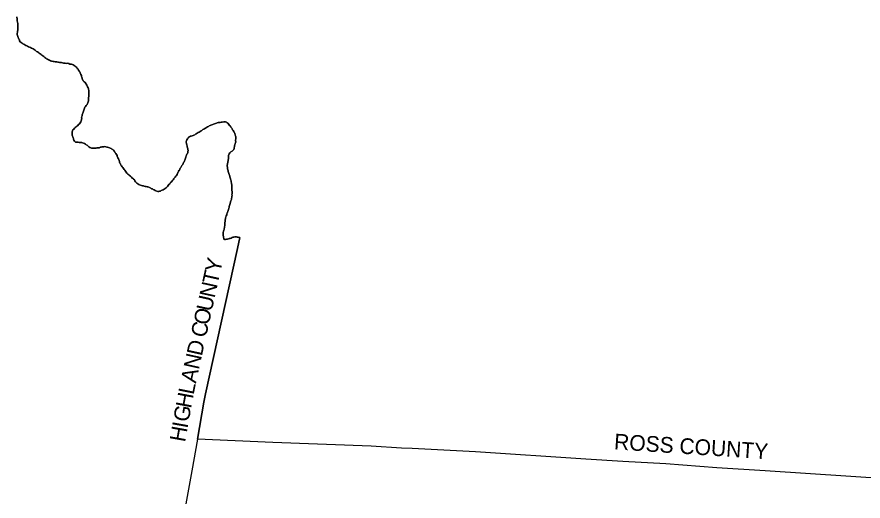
# Model space of a CAD drawing. Extents: x -51392 to 1635000, y 156707 to 696232.
# Drawn here: x 151547 to 205342, y 359420 to 390170 of the extents above; entities that cross this region are included whole.
import ezdxf

# ---------------------------------------------------------------- set-up
doc = ezdxf.new("R2010")
doc.units = 0
doc.layers.add('GM_X_Adjacent_County', color=7, linetype='Continuous')
doc.layers.add('GM_X_Adjacent_County_Text', color=7, linetype='Continuous')

msp = doc.modelspace()

# ---------------------------------------------------------------- linework, layer by layer
at = {"layer": 'GM_X_Adjacent_County'}
for points in [[(209682, 360646), (199125, 361332), (196035, 361533), (192807, 361777), (190062, 361926), (187719, 362082), (180708, 362551), (176670, 362753), (175993, 362777), (174068, 362897), (167808, 363138), (163023, 363354), (163438, 365695), (163533, 366233), (165575, 375472), (165728, 376165), (165686, 376168), (165620, 376175), (165557, 376187), (165501, 376193), (165447, 376198), (165393, 376206), (165333, 376188), (165279, 376188), (165221, 376151), (165158, 376119), (165104, 376097), (165050, 376093), (164996, 376074), (164934, 376060), (164880, 376050), (164806, 376038), (164752, 376033), (164698, 376057), (164691, 376109), (164685, 376167), (164671, 376220), (164662, 376280), (164662, 376336), (164654, 376390), (164665, 376480), (164687, 376558), (164708, 376616), (164720, 376672), (164732, 376731), (164741, 376785), (164745, 376843), (164757, 376913), (164768, 376979), (164770, 377043), (164771, 377109), (164777, 377167), (164777, 377217), (164781, 377272), (164798, 377340), (164816, 377400), (164837, 377462), (164857, 377534), (164883, 377590), (164900, 377654), (164920, 377712), (164932, 377768), (164957, 377820), (164971, 377872), (164993, 377948), (165020, 378014), (165032, 378074), (165043, 378136), (165055, 378194), (165073, 378252), (165094, 378310), (165118, 378427), (165147, 378489), (165185, 378579), (165196, 378643), (165200, 378713), (165206, 378763), (165229, 378823), (165217, 378877), (165229, 378959), (165228, 379011), (165226, 379078), (165217, 379148), (165215, 379198), (165213, 379272), (165218, 379334), (165212, 379396), (165208, 379447), (165203, 379505), (165197, 379565), (165198, 379633), (165170, 379685), (165158, 379754), (165147, 379806), (165129, 379896), (165104, 379958), (165090, 380011), (165074, 380061), (165056, 380113), (165037, 380163), (165017, 380217), (164996, 380282), (164978, 380342), (164970, 380396), (164951, 380460), (164943, 380513), (164924, 380625), (164918, 380685), (164918, 380761), (164931, 380813), (164939, 380869), (164949, 380921), (164962, 380974), (164976, 381036), (164980, 381086), (164999, 381148), (164999, 381198), (164997, 381248), (165004, 381308), (165008, 381362), (165016, 381430), (165047, 381482), (165091, 381548), (165155, 381612), (165222, 381648), (165286, 381698), (165332, 381755), (165351, 381812), (165367, 381866), (165383, 381930), (165388, 381982), (165410, 382056), (165430, 382122), (165443, 382182), (165455, 382236), (165451, 382296), (165446, 382360), (165460, 382412), (165472, 382476), (165457, 382562), (165442, 382612), (165427, 382665), (165391, 382780), (165364, 382836), (165331, 382893), (165289, 382956), (165261, 383007), (165234, 383059), (165201, 383112), (165156, 383173), (165117, 383224), (165068, 383283), (165020, 383340), (164979, 383397), (164916, 383452), (164864, 383495), (164811, 383506), (164759, 383505), (164705, 383506), (164592, 383492), (164528, 383477), (164462, 383458), (164404, 383457), (164340, 383456), (164282, 383445), (164227, 383424), (164169, 383405), (164109, 383386), (164054, 383369), (163994, 383344), (163941, 383319), (163885, 383298), (163831, 383270), (163778, 383245), (163717, 383204), (163661, 383181), (163609, 383148), (163544, 383115), (163483, 383084), (163425, 383049), (163356, 383014), (163303, 382967), (163253, 382938), (163198, 382899), (163132, 382860), (163075, 382827), (163006, 382786), (162950, 382751), (162897, 382720), (162847, 382690), (162794, 382659), (162744, 382632), (162687, 382613), (162627, 382606), (162577, 382597), (162522, 382558), (162460, 382525), (162444, 382474), (162399, 382420), (162359, 382366), (162327, 382310), (162308, 382256), (162308, 382204), (162318, 382152), (162326, 382101), (162349, 382045), (162365, 381965), (162374, 381911), (162396, 381852), (162408, 381800), (162417, 381744), (162427, 381676), (162417, 381622), (162402, 381566), (162382, 381506), (162358, 381454), (162323, 381394), (162309, 381338), (162283, 381262), (162266, 381190), (162238, 381130), (162219, 381078), (162203, 381025), (162173, 380974), (162143, 380918), (162122, 380857), (162088, 380800), (162035, 380738), (162011, 380686), (161975, 380616), (161934, 380560), (161894, 380506), (161884, 380446), (161829, 380392), (161813, 380334), (161781, 380280), (161753, 380228), (161726, 380158), (161686, 380102), (161639, 380046), (161609, 379990), (161551, 379932), (161519, 379878), (161472, 379822), (161418, 379756), (161378, 379704), (161317, 379651), (161259, 379575), (161215, 379521), (161168, 379459), (161126, 379403), (161072, 379367), (161027, 379311), (160973, 379277), (160911, 379226), (160845, 379198), (160789, 379162), (160724, 379140), (160672, 379113), (160610, 379109), (160560, 379075), (160504, 379081), (160440, 379096), (160384, 379114), (160331, 379142), (160271, 379181), (160219, 379209), (160161, 379241), (160107, 379260), (160050, 379288), (159984, 379335), (159926, 379363), (159874, 379369), (159820, 379379), (159760, 379398), (159708, 379408), (159645, 379420), (159591, 379437), (159531, 379451), (159465, 379467), (159413, 379488), (159349, 379512), (159293, 379536), (159234, 379573), (159180, 379609), (159128, 379646), (159082, 379696), (159049, 379750), (159021, 379813), (158959, 379857), (158928, 379909), (158876, 379934), (158822, 379992), (158773, 380046), (158709, 380093), (158661, 380145), (158602, 380187), (158542, 380256), (158494, 380320), (158457, 380375), (158415, 380427), (158363, 380475), (158316, 380544), (158278, 380596), (158230, 380656), (158185, 380713), (158157, 380765), (158122, 380837), (158096, 380890), (158078, 380948), (158059, 380998), (158039, 381056), (158031, 381109), (158002, 381159), (157970, 381211), (157944, 381265), (157929, 381320), (157917, 381372), (157869, 381434), (157838, 381496), (157802, 381547), (157770, 381597), (157735, 381647), (157693, 381698), (157641, 381742), (157587, 381778), (157534, 381811), (157480, 381839), (157426, 381865), (157370, 381884), (157314, 381896), (157262, 381904), (157208, 381917), (157141, 381931), (157077, 381925), (156999, 381926), (156947, 381920), (156897, 381898), (156847, 381890), (156787, 381859), (156737, 381855), (156685, 381857), (156635, 381847), (156583, 381838), (156533, 381830), (156469, 381828), (156415, 381832), (156351, 381837), (156297, 381843), (156238, 381865), (156182, 381884), (156116, 381924), (156060, 381975), (156008, 382019), (155949, 382053), (155897, 382090), (155841, 382126), (155785, 382142), (155717, 382175), (155665, 382185), (155608, 382197), (155556, 382202), (155504, 382204), (155448, 382210), (155390, 382206), (155322, 382211), (155262, 382225), (155204, 382280), (155158, 382336), (155151, 382386), (155145, 382440), (155120, 382498), (155093, 382556), (155087, 382607), (155059, 382657), (155054, 382715), (155049, 382771), (155051, 382825), (155064, 382881), (155080, 382935), (155109, 382991), (155165, 383049), (155206, 383108), (155256, 383144), (155304, 383196), (155359, 383237), (155411, 383283), (155472, 383330), (155522, 383376), (155576, 383440), (155619, 383501), (155636, 383567), (155648, 383629), (155651, 383683), (155665, 383743), (155658, 383808), (155685, 383895), (155697, 383949), (155716, 384009), (155746, 384063), (155757, 384131), (155777, 384195), (155796, 384257), (155819, 384313), (155839, 384375), (155862, 384429), (155912, 384488), (155953, 384546), (156003, 384604), (156040, 384664), (156060, 384717), (156077, 384781), (156095, 384833), (156102, 384893), (156104, 384948), (156105, 385000), (156107, 385052), (156112, 385114), (156119, 385184), (156123, 385284), (156128, 385344), (156125, 385396), (156117, 385460), (156112, 385513), (156104, 385567), (156091, 385617), (156073, 385671), (156044, 385722), (156018, 385780), (155983, 385832), (155951, 385897), (155918, 385947), (155880, 386002), (155815, 386055), (155764, 386113), (155728, 386172), (155697, 386222), (155687, 386282), (155666, 386337), (155650, 386389), (155643, 386447), (155613, 386513), (155594, 386566), (155576, 386616), (155539, 386678), (155505, 386729), (155468, 386789), (155431, 386846), (155387, 386900), (155348, 386951), (155292, 387003), (155241, 387040), (155181, 387081), (155129, 387127), (155076, 387156), (155016, 387172), (154964, 387177), (154908, 387180), (154854, 387206), (154797, 387219), (154739, 387225), (154675, 387216), (154615, 387228), (154553, 387231), (154499, 387242), (154441, 387248), (154375, 387267), (154319, 387273), (154264, 387282), (154198, 387305), (154140, 387305), (154086, 387312), (154028, 387320), (153968, 387317), (153906, 387329), (153846, 387338), (153795, 387355), (153737, 387369), (153679, 387388), (153611, 387420), (153548, 387449), (153486, 387482), (153432, 387514), (153381, 387553), (153327, 387596), (153264, 387650), (153202, 387697), (153135, 387746), (153081, 387788), (153026, 387831), (152962, 387876), (152908, 387916), (152855, 387951), (152801, 387983), (152750, 388024), (152696, 388059), (152638, 388099), (152581, 388142), (152529, 388164), (152467, 388189), (152402, 388226), (152350, 388248), (152288, 388273), (152229, 388307), (152171, 388332), (152109, 388363), (152052, 388401), (151984, 388432), (151924, 388459), (151871, 388495), (151817, 388540), (151750, 388597), (151720, 388651), (151703, 388709), (151675, 388760), (151646, 388816), (151626, 388874), (151599, 388929), (151579, 388989), (151552, 389049), (151563, 389107), (151569, 389147), (151573, 389171), (151584, 389223), (151590, 389276), (151595, 389338), (151601, 389394), (151602, 389494), (151607, 389544), (151609, 389610), (151606, 389678), (151604, 389736), (151590, 389853), (151568, 389903), (151569, 389965), (151563, 390017), (151554, 390079), (151548, 390130), (151547, 390180)], [(151547, 390180), (151548, 390130), (151554, 390079), (151563, 390017), (151569, 389965), (151568, 389903), (151590, 389853), (151604, 389736), (151606, 389678), (151609, 389610), (151607, 389544), (151602, 389494), (151601, 389394), (151595, 389338), (151590, 389276), (151584, 389223), (151573, 389171), (151569, 389147), (151563, 389107), (151552, 389049), (151579, 388989), (151599, 388929), (151626, 388874), (151646, 388816), (151675, 388760), (151703, 388709), (151720, 388651), (151750, 388597), (151817, 388540), (151871, 388495), (151924, 388459), (151984, 388432), (152052, 388401), (152109, 388363), (152171, 388332), (152229, 388307), (152288, 388273), (152350, 388248), (152402, 388226), (152467, 388189), (152529, 388164), (152581, 388142), (152638, 388099), (152696, 388059), (152750, 388024), (152801, 387983), (152855, 387951), (152908, 387916), (152962, 387876), (153026, 387831), (153081, 387788), (153135, 387746), (153202, 387697), (153264, 387650), (153327, 387596), (153381, 387553), (153432, 387514), (153486, 387482), (153548, 387449), (153611, 387420), (153679, 387388), (153737, 387369), (153795, 387355), (153846, 387338), (153906, 387329), (153968, 387317), (154028, 387320), (154086, 387312), (154140, 387305), (154198, 387305), (154264, 387282), (154319, 387273), (154375, 387267), (154441, 387248), (154499, 387242), (154553, 387231), (154615, 387228), (154675, 387216), (154739, 387225), (154797, 387219), (154854, 387206), (154908, 387180), (154964, 387177), (155016, 387172), (155076, 387156), (155129, 387127), (155181, 387081), (155241, 387040), (155292, 387003), (155348, 386951), (155387, 386900), (155431, 386846), (155468, 386789), (155505, 386729), (155539, 386678), (155576, 386616), (155594, 386566), (155613, 386513), (155643, 386447), (155650, 386389), (155666, 386337), (155687, 386282), (155697, 386222), (155728, 386172), (155764, 386113), (155815, 386055), (155880, 386002), (155918, 385947), (155951, 385897), (155983, 385832), (156018, 385780), (156044, 385722), (156073, 385671), (156091, 385617), (156104, 385567), (156112, 385513), (156117, 385460), (156125, 385396), (156128, 385344), (156123, 385284), (156119, 385184), (156112, 385114), (156107, 385052), (156105, 385000), (156104, 384948), (156102, 384893), (156095, 384833), (156077, 384781), (156060, 384717), (156040, 384664), (156003, 384604), (155953, 384546), (155912, 384488), (155862, 384429), (155839, 384375), (155819, 384313), (155796, 384257), (155777, 384195), (155757, 384131), (155746, 384063), (155716, 384009), (155697, 383949), (155685, 383895), (155658, 383808), (155665, 383743), (155651, 383683), (155648, 383629), (155636, 383567), (155619, 383501), (155576, 383440), (155522, 383376), (155472, 383330), (155411, 383283), (155359, 383237), (155304, 383196), (155256, 383144), (155206, 383108), (155165, 383049), (155109, 382991), (155080, 382935), (155064, 382881), (155051, 382825), (155049, 382771), (155054, 382715), (155059, 382657), (155087, 382607), (155093, 382556), (155120, 382498), (155145, 382440), (155151, 382386), (155158, 382336), (155204, 382280), (155262, 382225), (155322, 382211), (155390, 382206), (155448, 382210), (155504, 382204), (155556, 382202), (155608, 382197), (155665, 382185), (155717, 382175), (155785, 382142), (155841, 382126), (155897, 382090), (155949, 382053), (156008, 382019), (156060, 381975), (156116, 381924), (156182, 381884), (156238, 381865), (156297, 381843), (156351, 381837), (156415, 381832), (156469, 381828), (156533, 381830), (156583, 381838), (156635, 381847), (156685, 381857), (156737, 381855), (156787, 381859), (156847, 381890), (156897, 381898), (156947, 381920), (156999, 381926), (157077, 381925), (157141, 381931), (157208, 381917), (157262, 381904), (157314, 381896), (157370, 381884), (157426, 381865), (157480, 381839), (157534, 381811), (157587, 381778), (157641, 381742), (157693, 381698), (157735, 381647), (157770, 381597), (157802, 381547), (157838, 381496), (157869, 381434), (157917, 381372), (157929, 381320), (157944, 381265), (157970, 381211), (158002, 381159), (158031, 381109), (158039, 381056), (158059, 380998), (158078, 380948), (158096, 380890), (158122, 380837), (158157, 380765), (158185, 380713), (158230, 380656), (158278, 380596), (158316, 380544), (158363, 380475), (158415, 380427), (158457, 380375), (158494, 380320), (158542, 380256), (158602, 380187), (158661, 380145), (158709, 380093), (158773, 380046), (158822, 379992), (158876, 379934), (158928, 379909), (158959, 379857), (159021, 379813), (159049, 379750), (159082, 379696), (159128, 379646), (159180, 379609), (159234, 379573), (159293, 379536), (159349, 379512), (159413, 379488), (159465, 379467), (159531, 379451), (159591, 379437), (159645, 379420), (159708, 379408), (159760, 379398), (159820, 379379), (159874, 379369), (159926, 379363), (159984, 379335), (160050, 379288), (160107, 379260), (160161, 379241), (160219, 379209), (160271, 379181), (160331, 379142), (160384, 379114), (160440, 379096), (160504, 379081), (160560, 379075), (160610, 379109), (160672, 379113), (160724, 379140), (160789, 379162), (160845, 379198), (160911, 379226), (160973, 379277), (161027, 379311), (161072, 379367), (161126, 379403), (161168, 379459), (161215, 379521), (161259, 379575), (161317, 379651), (161378, 379704), (161418, 379756), (161472, 379822), (161519, 379878), (161551, 379932), (161609, 379990), (161639, 380046), (161686, 380102), (161726, 380158), (161753, 380228), (161781, 380280), (161813, 380334), (161829, 380392), (161884, 380446), (161894, 380506), (161934, 380560), (161975, 380616), (162011, 380686), (162035, 380738), (162088, 380800), (162122, 380857), (162143, 380918), (162173, 380974), (162203, 381025), (162219, 381078), (162238, 381130), (162266, 381190), (162283, 381262), (162309, 381338), (162323, 381394), (162358, 381454), (162382, 381506), (162402, 381566), (162417, 381622), (162427, 381676), (162417, 381744), (162408, 381800), (162396, 381852), (162374, 381911), (162365, 381965), (162349, 382045), (162326, 382101), (162318, 382152), (162308, 382204), (162308, 382256), (162327, 382310), (162359, 382366), (162399, 382420), (162444, 382474), (162460, 382525), (162522, 382558), (162577, 382597), (162627, 382606), (162687, 382613), (162744, 382632), (162794, 382659), (162847, 382690), (162897, 382720), (162950, 382751), (163006, 382786), (163075, 382827), (163132, 382860), (163198, 382899), (163253, 382938), (163303, 382967), (163356, 383014), (163425, 383049), (163483, 383084), (163544, 383115), (163609, 383148), (163661, 383181), (163717, 383204), (163778, 383245), (163831, 383270), (163885, 383298), (163941, 383319), (163994, 383344), (164054, 383369), (164109, 383386), (164169, 383405), (164227, 383424), (164282, 383445), (164340, 383456), (164404, 383457), (164462, 383458), (164528, 383477), (164592, 383492), (164705, 383506), (164759, 383505), (164811, 383506), (164864, 383495), (164916, 383452), (164979, 383397), (165020, 383340), (165068, 383283), (165117, 383224), (165156, 383173), (165201, 383112), (165234, 383059), (165261, 383007), (165289, 382956), (165331, 382893), (165364, 382836), (165391, 382780), (165427, 382665), (165442, 382612), (165457, 382562), (165472, 382476), (165460, 382412), (165446, 382360), (165451, 382296), (165455, 382236), (165443, 382182), (165430, 382122), (165410, 382056), (165388, 381982), (165383, 381930), (165367, 381866), (165351, 381812), (165332, 381755), (165286, 381698), (165222, 381648), (165155, 381612), (165091, 381548), (165047, 381482), (165016, 381430), (165008, 381362), (165004, 381308), (164997, 381248), (164999, 381198), (164999, 381148), (164980, 381086), (164976, 381036), (164962, 380974), (164949, 380921), (164939, 380869), (164931, 380813), (164918, 380761), (164918, 380685), (164924, 380625), (164943, 380513), (164951, 380460), (164970, 380396), (164978, 380342), (164996, 380282), (165017, 380217), (165037, 380163), (165056, 380113), (165074, 380061), (165090, 380011), (165104, 379958), (165129, 379896), (165147, 379806), (165158, 379754), (165170, 379685), (165198, 379633), (165197, 379565), (165203, 379505), (165208, 379447), (165212, 379396), (165218, 379334), (165213, 379272), (165215, 379198), (165217, 379148), (165226, 379078), (165228, 379011), (165229, 378959), (165217, 378877), (165229, 378823), (165206, 378763), (165200, 378713), (165196, 378643), (165185, 378579), (165147, 378489), (165118, 378427), (165094, 378310), (165073, 378252), (165055, 378194), (165043, 378136), (165032, 378074), (165020, 378014), (164993, 377948), (164971, 377872), (164957, 377820), (164932, 377768), (164920, 377712), (164900, 377654), (164883, 377590), (164857, 377534), (164837, 377462), (164816, 377400), (164798, 377340), (164781, 377272), (164777, 377217), (164777, 377167), (164771, 377109), (164770, 377043), (164768, 376979), (164757, 376913), (164745, 376843), (164741, 376785), (164732, 376731), (164720, 376672), (164708, 376616), (164687, 376558), (164665, 376480), (164654, 376390), (164662, 376336), (164662, 376280), (164671, 376220), (164685, 376167), (164691, 376109), (164698, 376057), (164752, 376033), (164806, 376038), (164880, 376050), (164934, 376060), (164996, 376074), (165050, 376093), (165104, 376097), (165158, 376119), (165221, 376151), (165279, 376188), (165333, 376188), (165393, 376206), (165447, 376198), (165501, 376193), (165557, 376187), (165620, 376175), (165686, 376168), (165728, 376165), (165575, 375472), (163533, 366233), (163438, 365695), (163023, 363354), (162663, 361330), (162292, 359241)]]:
    msp.add_lwpolyline(points, dxfattribs=at)

# ---------------------------------------------------------------- texts
at = {"layer": 'GM_X_Adjacent_County_Text'}
for s, rotation, p in [('Y', 77.5607, (164465, 373868)), ('T', 77.5621, (164303, 373137)), ('N', 77.5607, (164113, 372274)), ('U', 77.5618, (163922, 371410)), ('O', 77.5621, (163732, 370546)), ('C', 77.5608, (163557, 369752)), ('D', 77.5618, (163301, 368591)), ('N', 77.5685, (163110, 367728)), ('A', 77.8506, (162925, 366864)), ('L', 78.6364, (162778, 366135)), ('H', 79.3622, (162615, 365269)), ('G', 79.8562, (162460, 364400)), ('I', 79.8915, (162388, 363998)), ('H', 79.8894, (162233, 363127)), ('ROSS COUNTY', 356.2857, (189488, 362707))]:
    msp.add_text(s, height=1000, rotation=rotation, dxfattribs=at).set_placement(p)

doc.saveas('drawing.dxf')
